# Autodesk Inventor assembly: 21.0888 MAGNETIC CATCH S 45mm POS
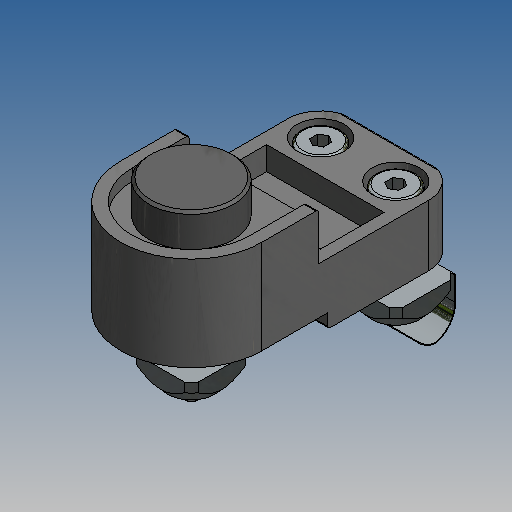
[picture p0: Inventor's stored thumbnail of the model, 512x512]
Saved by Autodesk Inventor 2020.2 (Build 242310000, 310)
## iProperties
Created: 2020-06
Part Number: 21.0888 MAGNETIC CATCH S 45mm POS
Document SubType Name: Assembly
Designer: amoles
Sending System: MiniTec Maschinenbau GmbH & Co.KG
Major Version: 4.0
Minor Version: 0.0
Format Version: 0.0
Product Id: MiniTec Maschinenbau GmbH & Co.KG
Art.-Nr.: 21.0888/0
L: -
Stück: 1
5: magnetic catch S
7: 21.0888/0
8: MiniTec Maschinenbau GmbH & Co KG
Bestellnummer: 21.0888/0
Beschreibung: magnetic catch S
Länge: -
Artikelnr: 21.0888/0
Lieferant: MiniTec Maschinenbau GmbH & Co KG
Author: amoles
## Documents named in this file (9)
- Y:\INVENTOR LIBRARIES\PARTS LIBRARY\HANDLES LOCKS STOPS\21.0888 MAGNETIC CATCH S 45mm POS.iam
- Y:\INVENTOR LIBRARIES\PARTS LIBRARY\HANDLES LOCKS STOPS\SUBCOMPONENTS\21.0888 MAGNETIC CATCH S BODY.ipt
- Y:\INVENTOR LIBRARIES\PARTS LIBRARY\HANDLES LOCKS STOPS\SUBCOMPONENTS\21.0888 CYLINDRICAL MAGNET.ipt
- Y:\INVENTOR LIBRARIES\PARTS LIBRARY\HANDLES LOCKS STOPS\SUBCOMPONENTS\21.0888 STEEL WASHER.ipt
- Y:\INVENTOR LIBRARIES\PARTS LIBRARY\FASTENING ELEMENTS\SCREWS COUNTERSUNK\21.1544 M3x16 CSUNK.ipt
- Y:\INVENTOR LIBRARIES\PARTS LIBRARY\FASTENING ELEMENTS\NUTS\21.1309 M3 SQUARE NUT.ipt
- 21.1309 M3.ipt
- Y:\INVENTOR LIBRARIES\PARTS LIBRARY\FASTENING ELEMENTS\SCREWS CAP\21.1222 M5X20.ipt
- Y:\INVENTOR LIBRARIES\PARTS LIBRARY\FASTENING ELEMENTS\NUTS\21.1320_2 M5 SQUARE NUT POS FXG.ipt
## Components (9 placed, 7 different names)
1. 21.0888 MAGNETIC CATCH BODY:1 — Insert:5, Insert:6, Angle:3, Angle:4, Mate:3, Mate:4, Insert:7, Angle:5
2. 21.0888 MAGNETIC CATCH CYLINDER — Insert:7, Insert:8
3. 21.0888 STEEL WASHER:1 — Insert:2, Insert:3, Insert:8
4. 21.1544 M3x16 CSUNK:1 — Insert:2
5. 21.1309 M3:1 — Insert:3, Angle:5
6. 21.1222 M5 x 20:1 — Insert:5, Mate:1
7. 21.1222 M5 x 20:2 — Insert:6, Mate:2
8. 21.1320_2 M5 SQUARE NUT POS FXG:1 — Mate:1, Angle:3, Mate:3
9. 21.1320_2 M5 SQUARE NUT POS FXG:2 — Mate:2, Angle:4, Mate:4
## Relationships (13: Insert 6, Mate 4, Angle 3)
- Insert:2: 21.0888 STEEL WASHER:1 ↔ 21.1544 M3x16 CSUNK:1
- Insert:3: 21.0888 STEEL WASHER:1 ↔ 21.1309 M3:1
- Insert:5: 21.0888 MAGNETIC CATCH BODY:1 ↔ 21.1222 M5 x 20:1
- Insert:6: 21.0888 MAGNETIC CATCH BODY:1 ↔ 21.1222 M5 x 20:2
- Mate:1: 21.1222 M5 x 20:1 ↔ 21.1320_2 M5 SQUARE NUT POS FXG:1
- Mate:2: 21.1222 M5 x 20:2 ↔ 21.1320_2 M5 SQUARE NUT POS FXG:2
- Angle:3: 21.0888 MAGNETIC CATCH BODY:1 ↔ 21.1320_2 M5 SQUARE NUT POS FXG:1
- Angle:4: 21.0888 MAGNETIC CATCH BODY:1 ↔ 21.1320_2 M5 SQUARE NUT POS FXG:2
- Mate:3: 21.0888 MAGNETIC CATCH BODY:1 ↔ 21.1320_2 M5 SQUARE NUT POS FXG:1
- Mate:4: 21.0888 MAGNETIC CATCH BODY:1 ↔ 21.1320_2 M5 SQUARE NUT POS FXG:2
- Insert:7: 21.0888 MAGNETIC CATCH BODY:1 ↔ 21.0888 MAGNETIC CATCH CYLINDER
- Insert:8: 21.0888 MAGNETIC CATCH CYLINDER ↔ 21.0888 STEEL WASHER:1
- Angle:5: 21.0888 MAGNETIC CATCH BODY:1 ↔ 21.1309 M3:1
